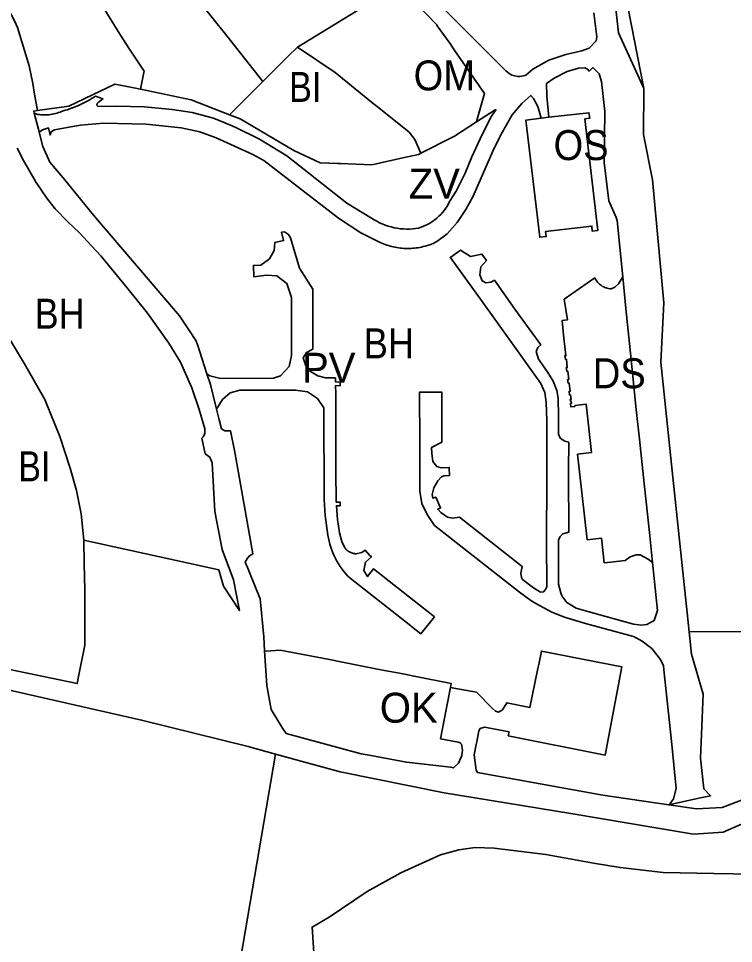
# Model space of a CAD drawing. Extents: x -650451 to -642268, y -1075216 to -1066610.
# Drawn here: x -645771.2 to -645413.5, y -1070883.4 to -1070420.9 of the extents above; entities that cross this region are included whole.
import ezdxf

# ---------------------------------------------------------------- set-up
doc = ezdxf.new("R2010")
doc.units = 0
doc.header["$LTSCALE"] = 6
doc.layers.add('1', color=7, linetype='Continuous', lineweight=35)
doc.layers.add('2', color=7, linetype='Continuous')
doc.layers.add('3', color=7, linetype='Continuous')

msp = doc.modelspace()

# ---------------------------------------------------------------- linework, layer by layer
at = {"layer": '1'}
for p, q in [((-645631.63, -1070435.3), (-645581.88, -1070404.79)), ((-645648.9, -1070452.38), (-645665.6, -1070469.04)), ((-645477.83, -1070467.43), (-645479.45, -1070452.44)), ((-645477.83, -1070467.43), (-645478.2, -1070492.9)), ((-645509.73, -1070470.79), (-645505.89, -1070470.28)), ((-645647.06, -1070549.3), (-645641.94, -1070549.53)), ((-645467.29, -1070565.95), (-645468.87, -1070550.15)), ((-645623.96, -1070586.18), (-645623.91, -1070556.28)), ((-645640.17, -1070599.5), (-645635.73, -1070594.86)), ((-645625.66, -1070597), (-645627.49, -1070594.56)), ((-645625.66, -1070597), (-645621.44, -1070599.65)), ((-645612.48, -1070608.38), (-645612.51, -1070604.47)), ((-645669.11, -1070611.38), (-645672.04, -1070616.26)), ((-645612.48, -1070608.38), (-645612.47, -1070611.33)), ((-645612.37, -1070644.92), (-645612.47, -1070611.33)), ((-645458.17, -1070653.38), (-645460.44, -1070631.3)), ((-645458.17, -1070653.38), (-645455.53, -1070677.99)), ((-645614.974, -1070685.241), (-645614.475, -1070686.701)), ((-645607.644, -1070685.968), (-645607.913, -1070685.639)), ((-645605.231, -1070687.804), (-645605.622, -1070687.603)), ((-645602.739, -1070688.492), (-645603.16, -1070688.44)), ((-645607.388, -1070698.566), (-645608.38, -1070697.401)), ((-645448.36, -1070746.61), (-645448.55, -1070744.43)), ((-645448.36, -1070746.61), (-645444.5, -1070782.23)), ((-645442.16, -1070805.9), (-645444.5, -1070782.23))]:
    msp.add_line(p, q, dxfattribs=at)
for points in [[(-645458.32, -1070455.91), (-645471, -1070391), (-645481.67, -1070345.39), (-645481.65, -1070342.07), (-645483.34, -1070321.17), (-645484.27, -1070309.7), (-645485.21, -1070298.03), (-645487.361, -1070271.37)], [(-645837.64, -1070295.83), (-645834.26, -1070303.42), (-645832.25, -1070305.65), (-645828.22, -1070310.11), (-645806.76, -1070328.54), (-645794.16, -1070338.86), (-645775.346, -1070326.977), (-645755.75, -1070371.21), (-645720.48, -1070428.75), (-645715.56, -1070436.27), (-645708.28, -1070447.28), (-645708.42, -1070447.94), (-645710.14, -1070456.31)], [(-645761.61, -1070466.87), (-645763.08, -1070458.8), (-645764.06, -1070453.46), (-645765.74, -1070444.55), (-645771.6, -1070425.37), (-645772.93, -1070422.45), (-645774.64, -1070419.2), (-645776.69, -1070415.31), (-645779.05, -1070410.84), (-645781.68, -1070407.25), (-645782.24, -1070406.48), (-645782.7, -1070405.88), (-645788.04, -1070398.98), (-645791.08, -1070394.9), (-645791.28, -1070394.68), (-645794.6, -1070391.11), (-645810.27, -1070374.27), (-645820.27, -1070363.94), (-645828.93, -1070354.9), (-645831.79, -1070351.94), (-645857.6, -1070325.28), (-645863.12, -1070319.59)], [(-645648.9, -1070452.38), (-645648.95, -1070452.32), (-645666.99, -1070429.58), (-645681.89, -1070410.81), (-645682.02, -1070410.65), (-645683.52, -1070411.71), (-645697.44, -1070391.91), (-645701.32, -1070386.14), (-645705.74, -1070379.56), (-645713.73, -1070365.9), (-645692.34, -1070349.34), (-645668.02, -1070330.52)], [(-645488.99, -1070362.96), (-645482.16, -1070375.96), (-645476.12, -1070393.13), (-645472.61, -1070413.13), (-645470.99, -1070428.07), (-645461.32, -1070449.31), (-645458.32, -1070455.91)], [(-645581.88, -1070404.79), (-645567.63, -1070418.2), (-645561.93, -1070424.15), (-645561.67, -1070424.51), (-645555.45, -1070433.22), (-645552.84, -1070437.12), (-645538.09, -1070458.33), (-645541.31, -1070470.02), (-645542.06, -1070472.61)], [(-645483.29, -1070417.99), (-645481.93, -1070430.04), (-645482.18, -1070432.13), (-645485.67, -1070435.7), (-645489.34, -1070437.05), (-645497.33, -1070438.82), (-645505.88, -1070441.74), (-645513.81, -1070446.24), (-645517.44, -1070449.23), (-645517.95, -1070449.45), (-645520.4, -1070449.87), (-645521.41, -1070449.84), (-645522.95, -1070449.61), (-645524.42, -1070449.16), (-645525.75, -1070448.41), (-645527.34, -1070447.1), (-645558.36, -1070416.1)], [(-645631.63, -1070435.3), (-645636.42, -1070439.93), (-645648.9, -1070452.38)], [(-645569.97, -1070488.3), (-645572.86, -1070481.41), (-645575.7, -1070477.77), (-645590.966, -1070465.607), (-645594.62, -1070462.7), (-645612.77, -1070447.82), (-645631.63, -1070435.3)], [(-645505.89, -1070470.28), (-645506.94, -1070459.72), (-645507.07, -1070453.47), (-645503.21, -1070450.74), (-645496.76, -1070447.39), (-645491.1, -1070445.67), (-645487.86, -1070445.62), (-645486.55, -1070446.19), (-645485.77, -1070447.23), (-645483.85, -1070445.46), (-645480.71, -1070448.54), (-645479.45, -1070452.44)], [(-645710.14, -1070456.31), (-645716.87, -1070454.93), (-645723.02, -1070453.66), (-645734.2, -1070459.05), (-645746.01, -1070464.75), (-645761.61, -1070466.87)], [(-645763.27, -1070468.21), (-645761.52, -1070468.88), (-645760.725, -1070468.979), (-645759.923, -1070469.051), (-645759.117, -1070469.095), (-645758.307, -1070469.111), (-645757.495, -1070469.099), (-645756.682, -1070469.058), (-645755.871, -1070468.989), (-645755.061, -1070468.891), (-645754.256, -1070468.765), (-645753.456, -1070468.61), (-645752.663, -1070468.428), (-645751.879, -1070468.218), (-645751.104, -1070467.982), (-645750.34, -1070467.72), (-645749.588, -1070467.432), (-645748.85, -1070467.12), (-645747.78, -1070466.818), (-645746.714, -1070466.494), (-645745.654, -1070466.148), (-645744.6, -1070465.779), (-645743.554, -1070465.389), (-645742.515, -1070464.976), (-645741.484, -1070464.542), (-645740.462, -1070464.086), (-645739.45, -1070463.609), (-645738.448, -1070463.111), (-645737.458, -1070462.593), (-645736.479, -1070462.055), (-645735.512, -1070461.497), (-645734.558, -1070460.92), (-645733.617, -1070460.324), (-645732.69, -1070459.71), (-645728.96, -1070461.09), (-645731.29, -1070462.95), (-645731.417, -1070463.016), (-645731.538, -1070463.102), (-645731.647, -1070463.206), (-645731.742, -1070463.326), (-645731.818, -1070463.459), (-645731.874, -1070463.599), (-645731.909, -1070463.743), (-645731.923, -1070463.886), (-645731.918, -1070464.03), (-645731.892, -1070464.175), (-645731.845, -1070464.319), (-645731.777, -1070464.456), (-645731.691, -1070464.582), (-645731.588, -1070464.692), (-645731.473, -1070464.786), (-645731.35, -1070464.86), (-645722.28, -1070464.74), (-645708.17, -1070465.09), (-645694.33, -1070466.36), (-645684.23, -1070467.84), (-645673.56, -1070470.8), (-645665.15, -1070474.28), (-645662.39, -1070475.35), (-645650.63, -1070481.24), (-645636.93, -1070489.64), (-645606.97, -1070513.16), (-645594.57, -1070520.71), (-645593.298, -1070521.526), (-645591.978, -1070522.287), (-645590.614, -1070522.989), (-645589.209, -1070523.628), (-645587.767, -1070524.201), (-645586.295, -1070524.705), (-645584.796, -1070525.137), (-645583.276, -1070525.497), (-645581.74, -1070525.781), (-645580.194, -1070525.989), (-645578.643, -1070526.122), (-645577.093, -1070526.179), (-645575.55, -1070526.16), (-645574.018, -1070526.068), (-645572.503, -1070525.904), (-645571.01, -1070525.67), (-645569.793, -1070525.275), (-645568.586, -1070524.813), (-645567.395, -1070524.286), (-645566.225, -1070523.693), (-645565.082, -1070523.035), (-645563.97, -1070522.316), (-645562.894, -1070521.536), (-645561.86, -1070520.699), (-645560.872, -1070519.809), (-645559.934, -1070518.869), (-645559.049, -1070517.883), (-645558.221, -1070516.856), (-645557.453, -1070515.794), (-645556.745, -1070514.7), (-645556.101, -1070513.58), (-645555.52, -1070512.44), (-645552.21, -1070507.22), (-645547.8, -1070498.2), (-645544.34, -1070490.01), (-645539.29, -1070478.88), (-645534.54, -1070469.76), (-645532.28, -1070466.32)], [(-645509.73, -1070470.79), (-645511.36, -1070464.95), (-645513.49, -1070460.97), (-645514.92, -1070459.32), (-645519.4, -1070463.48), (-645524.17, -1070469.11), (-645529.8, -1070479.03), (-645533.96, -1070487.3), (-645543.74, -1070509.74), (-645547.32, -1070516.32), (-645551.64, -1070522.86), (-645556.72, -1070528.54), (-645561.93, -1070532.44), (-645563.79, -1070533.39), (-645564.581, -1070533.705), (-645565.385, -1070534), (-645566.2, -1070534.277), (-645567.025, -1070534.533), (-645567.86, -1070534.768), (-645568.704, -1070534.983), (-645569.557, -1070535.175), (-645570.417, -1070535.346), (-645571.284, -1070535.495), (-645572.157, -1070535.621), (-645573.034, -1070535.723), (-645573.916, -1070535.803), (-645574.8, -1070535.859), (-645575.687, -1070535.891), (-645576.575, -1070535.9), (-645577.463, -1070535.885), (-645578.35, -1070535.847), (-645579.236, -1070535.784), (-645580.119, -1070535.698), (-645580.999, -1070535.589), (-645581.874, -1070535.457), (-645582.743, -1070535.301), (-645583.607, -1070535.123), (-645584.463, -1070534.922), (-645585.311, -1070534.7), (-645586.151, -1070534.456), (-645586.98, -1070534.191), (-645587.8, -1070533.906), (-645588.608, -1070533.6), (-645589.405, -1070533.275), (-645590.189, -1070532.932), (-645590.96, -1070532.57), (-645599.98, -1070528), (-645611.05, -1070520.81), (-645648.38, -1070491.95), (-645653.92, -1070488.85), (-645672.29, -1070480.56), (-645680.39, -1070477.65), (-645689.72, -1070475.58), (-645707.28, -1070473.72), (-645728.67, -1070473.29), (-645740.06, -1070474.19), (-645743.09, -1070474.76), (-645753.11, -1070476.57), (-645754.83, -1070477.59), (-645755.38, -1070479.08), (-645756.18, -1070475.61), (-645759.19, -1070476.56), (-645760.79, -1070477.75)], [(-645665.6, -1070469.04), (-645684.78, -1070461.52), (-645710.14, -1070456.31)], [(-645435.711, -1070727.497), (-645444.47, -1070643.85), (-645449.82, -1070592.72), (-645448.36, -1070563), (-645454.02, -1070501.52), (-645458.46, -1070478.86), (-645458.32, -1070455.91)], [(-645763.27, -1070468.21), (-645763.54, -1070467.17), (-645761.61, -1070466.87)], [(-645760.79, -1070477.75), (-645761.2, -1070476.16), (-645763.27, -1070468.21)], [(-645665.6, -1070469.04), (-645660.29, -1070471.12), (-645633.35, -1070486.91), (-645620.22, -1070493), (-645611.52, -1070493.37), (-645610.16, -1070493.43), (-645594.41, -1070494.08), (-645577.47, -1070490.3), (-645571.13, -1070488.89), (-645569.97, -1070488.3)], [(-645532.28, -1070466.32), (-645532.78, -1070466.64), (-645542.06, -1070472.61)], [(-645505.89, -1070470.28), (-645485.84, -1070468.01), (-645485.42, -1070470.79), (-645487.81, -1070471.13), (-645481.37, -1070526.93), (-645484.14, -1070527.28), (-645484.31, -1070524.66), (-645507.48, -1070527.34), (-645507.28, -1070529.96), (-645510.38, -1070530.29), (-645517.37, -1070471.66), (-645509.73, -1070470.79)], [(-645542.06, -1070472.61), (-645553.08, -1070479.7), (-645569.97, -1070488.3)], [(-645760.79, -1070477.75), (-645758.97, -1070484.82), (-645755.43, -1070492.66), (-645748.83, -1070500.53), (-645733.62, -1070519.2), (-645690.55, -1070569.6), (-645688.56, -1070572.64), (-645685.61, -1070577.02), (-645682.52, -1070581.87), (-645681.57, -1070583.92), (-645676.88, -1070598.59)], [(-645771.89, -1070485.66), (-645768.61, -1070491.93), (-645762.29, -1070502.85), (-645756.94, -1070510.81), (-645752.81, -1070516.11), (-645746.29, -1070522.79), (-645740.88, -1070527.97), (-645734.6, -1070534.63), (-645729.94, -1070539.58), (-645716.91, -1070555.35), (-645706.56, -1070568.19), (-645695.89, -1070583.17), (-645690.04, -1070592.67), (-645684.45, -1070605.57), (-645680.76, -1070616.33), (-645677.94, -1070626.03), (-645677.86, -1070628.21), (-645678.23, -1070629.21), (-645678.8, -1070630.03), (-645679.46, -1070630.75), (-645677.83, -1070638.56), (-645675.38, -1070640.29), (-645674.2, -1070643.07), (-645672.92, -1070667.42), (-645669.28, -1070686.41), (-645663.52, -1070701.56), (-645660.67, -1070716.93), (-645668.66, -1070704.8), (-645670.99, -1070696.59), (-645738.54, -1070681.67)], [(-645738.54, -1070681.67), (-645739.76, -1070668.59), (-645742.15, -1070656.97), (-645745.26, -1070645.72), (-645750.46, -1070629.86), (-645758.05, -1070611.4), (-645768.08, -1070593.53), (-645776.12, -1070580.27), (-645792.2, -1070553.77), (-645800.24, -1070540.51), (-645808.28, -1070527.27), (-645816.32, -1070514.02), (-645824.36, -1070500.76), (-645831.88, -1070488.37)], [(-645468.87, -1070550.15), (-645471.73, -1070521.93), (-645472.2, -1070520.36), (-645475.9, -1070512.13), (-645478.2, -1070492.9)], [(-645639.52, -1070527.73), (-645638.51, -1070531.91), (-645642.94, -1070532.95), (-645643.32, -1070536.98), (-645645.6, -1070541.03), (-645649.93, -1070544.17)], [(-645639.52, -1070527.73), (-645638.05, -1070527.53), (-645636.04, -1070528.83), (-645635.01, -1070530.52), (-645630.51, -1070545.8), (-645623.91, -1070556.28)], [(-645448.55, -1070744.43), (-645449.99, -1070741.54), (-645451.21, -1070739.85), (-645454.4, -1070735.98), (-645459.19, -1070732.3), (-645462.19, -1070730.5), (-645463.53, -1070729.98), (-645487.49, -1070723.42), (-645497.98, -1070720.16), (-645504.43, -1070717.68), (-645512.32, -1070713.33), (-645514.9, -1070711.87), (-645520.56, -1070707.79), (-645563, -1070674.39), (-645566.77, -1070668.94), (-645569.37, -1070663.42), (-645570.41, -1070657.25), (-645570.44, -1070633.21), (-645570.56, -1070607.66), (-645559.45, -1070607.71), (-645559.42, -1070632.82), (-645564.48, -1070635.35), (-645564.44, -1070638.26), (-645563.9, -1070642.47), (-645561.92, -1070644.94), (-645559.54, -1070645.51), (-645555.71, -1070645.39), (-645555.61, -1070649.48), (-645558.39, -1070649.6), (-645559.61, -1070650.14), (-645561.41, -1070652.05), (-645563.36, -1070655.51), (-645564.29, -1070658.96), (-645563.82, -1070660.8), (-645562.43, -1070660.23), (-645561.72, -1070661.77), (-645560.68, -1070664.11), (-645559.99, -1070665.62), (-645561.42, -1070666.27), (-645559.93, -1070667.85), (-645556.6, -1070670.16), (-645554.1, -1070670.79), (-645550.52, -1070670.21), (-645519.21, -1070694.89), (-645519.82, -1070698.19), (-645519.61, -1070700.46), (-645519.11, -1070701.39), (-645513.46, -1070705.56), (-645510.1, -1070707.67), (-645508.52, -1070707.65), (-645507.49, -1070706.46), (-645506.95, -1070705.03), (-645506.96, -1070682.29), (-645506.93, -1070651.11), (-645506.94, -1070622.09), (-645507.15, -1070612.93), (-645507.82, -1070607.9), (-645509.91, -1070603.33), (-645525.63, -1070581.2), (-645539.2, -1070562.35), (-645555.16, -1070540.29), (-645554.95, -1070540.26), (-645550.03, -1070536.72), (-645545.05, -1070539.94), (-645539.38, -1070538.66), (-645537.08, -1070541.92), (-645539.82, -1070545.06), (-645540.36, -1070549.11), (-645539.18, -1070551.99), (-645537.43, -1070553.01), (-645534.8, -1070552.67), (-645533.11, -1070551.79), (-645522.86, -1070566.18), (-645509.89, -1070584.1), (-645511.36, -1070585.42), (-645512.13, -1070587.38), (-645511.61, -1070589.63), (-645511.05, -1070591.31), (-645510.6, -1070591.9), (-645506.33, -1070597.84), (-645503.65, -1070602.19), (-645501.92, -1070606.98), (-645501.25, -1070610.78), (-645501.02, -1070619.82), (-645500.99, -1070625.75), (-645501.01, -1070628.79), (-645500.12, -1070630.71), (-645497.87, -1070632.29), (-645495.87, -1070632.81), (-645496, -1070646.36), (-645495.96, -1070648.03), (-645495.89, -1070677.71), (-645498.84, -1070678.61), (-645500.19, -1070679.84), (-645500.97, -1070681.8), (-645500.99, -1070703.81), (-645499.8, -1070708.06), (-645499.37, -1070709.57), (-645496.83, -1070712.83), (-645492.2, -1070715.68), (-645486.43, -1070717.48)], [(-645647.06, -1070549.3), (-645653.51, -1070550.01), (-645653.6, -1070544.35), (-645649.93, -1070544.17)], [(-645634.55, -1070560.44), (-645636.92, -1070553.36), (-645641.94, -1070549.53)], [(-645453.99, -1070692.88), (-645456.26, -1070691.25), (-645460.24, -1070689.15), (-645462.22, -1070689.01), (-645465.19, -1070690.01), (-645467.67, -1070691.87), (-645474.87, -1070692.74), (-645478.16, -1070693.14), (-645479.54, -1070680.67), (-645486.67, -1070681.54), (-645490.59, -1070647.61), (-645490.75, -1070646.01), (-645491.49, -1070638.79), (-645484.53, -1070637.98), (-645487.19, -1070613.79), (-645492.84, -1070614.42), (-645492.81, -1070614.88), (-645494.88, -1070615.07), (-645495.08, -1070613.33), (-645494.56, -1070613.26), (-645494.7, -1070612.17), (-645495.08, -1070612.22), (-645495.15, -1070611.38), (-645494.78, -1070611.36), (-645495.06, -1070609.1), (-645495.56, -1070609.16), (-645495.76, -1070607.36), (-645495.26, -1070607.33), (-645495.72, -1070603.18), (-645496.25, -1070603.23), (-645496.47, -1070601.42), (-645495.92, -1070601.39), (-645496.42, -1070597.2), (-645496.94, -1070597.25), (-645497.12, -1070595.47), (-645496.64, -1070595.38), (-645497.09, -1070591.24), (-645497.6, -1070591.26), (-645497.88, -1070589.46), (-645497.3, -1070589.44), (-645498.42, -1070580.7), (-645498.6, -1070579.19), (-645499.25, -1070571.93), (-645496.52, -1070571.56), (-645498.26, -1070561.27), (-645482.83, -1070550.63), (-645482.557, -1070551.178), (-645482.244, -1070551.716), (-645481.889, -1070552.239), (-645481.495, -1070552.742), (-645481.064, -1070553.221), (-645480.596, -1070553.673), (-645480.095, -1070554.093), (-645479.565, -1070554.477), (-645479.009, -1070554.823), (-645478.431, -1070555.129), (-645477.837, -1070555.391), (-645477.229, -1070555.611), (-645476.615, -1070555.785), (-645475.997, -1070555.916), (-645475.381, -1070556.004), (-645474.77, -1070556.05), (-645472.89, -1070555.29), (-645471.06, -1070553.59), (-645468.87, -1070550.15)], [(-645634.55, -1070560.44), (-645634.53, -1070589.43), (-645635.73, -1070594.86)], [(-645467.29, -1070565.95), (-645464.71, -1070591.33), (-645462.27, -1070614.86), (-645460.44, -1070631.3)], [(-645623.96, -1070586.18), (-645627.06, -1070587.88), (-645628.71, -1070590.62), (-645627.49, -1070594.56)], [(-645640.17, -1070599.5), (-645643.67, -1070600.77), (-645670.06, -1070600.85), (-645675.52, -1070599.54), (-645676.88, -1070598.59)], [(-645676.88, -1070598.59), (-645675.18, -1070603.92), (-645672.04, -1070616.26)], [(-645612.52, -1070600.61), (-645617.53, -1070600.63), (-645621.44, -1070599.65)], [(-645612.52, -1070600.61), (-645612.51, -1070602.61), (-645610.19, -1070602.7), (-645610.23, -1070604.51), (-645612.51, -1070604.47)], [(-645669.11, -1070611.38), (-645665.28, -1070608.14), (-645660.51, -1070606.77), (-645632.58, -1070606.68), (-645626.66, -1070607.61), (-645621.63, -1070610.87), (-645618.48, -1070615.64)], [(-645672.04, -1070616.26), (-645670.69, -1070621.55), (-645669.56, -1070625.99), (-645667.9, -1070627.04), (-645665.09, -1070627.11), (-645662.98, -1070637.66), (-645653.91, -1070688.62), (-645655.57, -1070689.58), (-645656.61, -1070690.71), (-645657.42, -1070692.11), (-645657.74, -1070692.82), (-645656.16, -1070696.6), (-645655.98, -1070697.02), (-645650.34, -1070711.07), (-645648.49, -1070730.06), (-645648.06, -1070737.06)], [(-645617.83, -1070669.4), (-645618.25, -1070661.44), (-645618.48, -1070615.64)], [(-645612.37, -1070644.92), (-645612.35, -1070646.95), (-645612.22, -1070662.75), (-645610.31, -1070662.66), (-645610.28, -1070664.52)], [(-645610.5, -1070678.09), (-645611.57, -1070671.42), (-645612.16, -1070664.56), (-645610.28, -1070664.52)], [(-645617.83, -1070669.4), (-645616.34, -1070679.3), (-645616.093, -1070680.793), (-645615.783, -1070682.283)], [(-645738.54, -1070681.67), (-645738.27, -1070693.6), (-645738.04, -1070706.52), (-645737.9, -1070733.79), (-645737.99, -1070734.24), (-645741.06, -1070749.97), (-645741.73, -1070753.43), (-645780.43, -1070745.4), (-645784.44, -1070740.92)], [(-645610.5, -1070678.09), (-645609.39, -1070682.34), (-645608.16, -1070685.3), (-645607.913, -1070685.639)], [(-645451.46, -1070716.89), (-645453.99, -1070692.88), (-645455.53, -1070677.99)], [(-645614.974, -1070685.241), (-645615.41, -1070683.767), (-645615.783, -1070682.283)], [(-645613.292, -1070689.56), (-645613.914, -1070688.142), (-645614.475, -1070686.701)], [(-645607.644, -1070685.968), (-645607.354, -1070686.283), (-645607.043, -1070686.584), (-645606.713, -1070686.868), (-645606.365, -1070687.134), (-645606.001, -1070687.379), (-645605.622, -1070687.603)], [(-645599.42, -1070687.99), (-645597.79, -1070686.69), (-645595.51, -1070689.22), (-645594.59, -1070690.02), (-645597.59, -1070692.68), (-645598.41, -1070696.88), (-645596.64, -1070699.96), (-645593.56, -1070696.04), (-645563.12, -1070720.01)], [(-645613.292, -1070689.56), (-645612.61, -1070690.953), (-645611.871, -1070692.316)], [(-645605.231, -1070687.804), (-645604.829, -1070687.981), (-645604.418, -1070688.134), (-645604.002, -1070688.261), (-645603.582, -1070688.363), (-645603.16, -1070688.44)], [(-645602.739, -1070688.492), (-645602.32, -1070688.52), (-645599.42, -1070687.99)], [(-645610.227, -1070694.938), (-645611.076, -1070693.645), (-645611.871, -1070692.316)], [(-645610.227, -1070694.938), (-645609.328, -1070696.191), (-645608.38, -1070697.401)], [(-645607.388, -1070698.566), (-645606.353, -1070699.683), (-645605.28, -1070700.75), (-645574.9, -1070724.61), (-645574.53, -1070724.94)], [(-645486.43, -1070717.48), (-645463.56, -1070723.81), (-645459.6, -1070724.28), (-645456.77, -1070723.99), (-645453.2, -1070721.89), (-645451.46, -1070716.89)], [(-645563.12, -1070720.01), (-645569.86, -1070728.57), (-645574.53, -1070724.94)], [(-645435.711, -1070727.497), (-645202.41, -1070726.571), (-645197.539, -1070753.128)], [(-645435.711, -1070727.497), (-645434.53, -1070738.77), (-645428.73, -1070758.67), (-645430, -1070790.68), (-645428.39, -1070806.09), (-645424.969, -1070809.563), (-645429.993, -1070810.647)], [(-645642.52, -1070788.7), (-645656.2, -1070784.96), (-645709.54, -1070771.74), (-645781.62, -1070755.42), (-645785.75, -1070754.48), (-645865, -1070735.66), (-645891.35, -1070731.13), (-645906.373, -1070728.716)], [(-645648.06, -1070737.06), (-645647.26, -1070737.17), (-645640.34, -1070736.72), (-645615.58, -1070741.49), (-645609.94, -1070742.59), (-645591.59, -1070746.19), (-645588.05, -1070746.85), (-645580.59, -1070748.22), (-645576.47, -1070749.04), (-645573.3, -1070749.75), (-645554.7, -1070753.41), (-645555.05, -1070755.49)], [(-645648.06, -1070737.06), (-645646.91, -1070754.37), (-645644.8, -1070766.37), (-645639.12, -1070775.74), (-645637.33, -1070778.34), (-645599.74, -1070788.56), (-645595.66, -1070789.32), (-645577.07, -1070792.77), (-645555.03, -1070795.23), (-645553.53, -1070795.66), (-645551.13, -1070793.3), (-645549.4, -1070789.42), (-645549.07, -1070786.78), (-645549.49, -1070783.81), (-645550.29, -1070783.02), (-645551.22, -1070782.7), (-645560.03, -1070781.11), (-645557.11, -1070765.58), (-645555.05, -1070755.49)], [(-645555.05, -1070755.49), (-645553.37, -1070755.82), (-645542.02, -1070757.79), (-645534.05, -1070765.87), (-645532.57, -1070767.28), (-645531.12, -1070767.68), (-645529.02, -1070766.53), (-645526.87, -1070763.04), (-645515.34, -1070765.49), (-645511.34, -1070745.83), (-645510.95, -1070743.9), (-645509.58, -1070737.17), (-645469.29, -1070745.15), (-645477.63, -1070789.21), (-645526.15, -1070779.53), (-645525.76, -1070777.58), (-645537.02, -1070775.46), (-645538.13, -1070775.3), (-645540.25, -1070775.93), (-645540.94, -1070777.05), (-645541.96, -1070782.5), (-645542.26, -1070783.94), (-645543.27, -1070789.16), (-645542.15, -1070796.73), (-645541.56, -1070797.841), (-645478.83, -1070809.27), (-645445.81, -1070814.06)], [(-645202.96, -1070752.89), (-645285.11, -1070750.69), (-645298.41, -1070751.48), (-645312.2, -1070753.77), (-645325.82, -1070757.94), (-645342.41, -1070765.76), (-645354.98, -1070774.28), (-645398.04, -1070805.44), (-645407.37, -1070810.95), (-645419.18, -1070815.44), (-645432.07, -1070816.05), (-645445.81, -1070814.06)], [(-645583.18, -1071010.7), (-645637.94, -1070997.4), (-645676.292, -1070985.89), (-645642.52, -1070788.7)], [(-645642.52, -1070788.7), (-645625, -1070793.5), (-645610.25, -1070797.55), (-645558.3, -1070808), (-645494.82, -1070818.45), (-645452.31, -1070825.52), (-645433.49, -1070828.76), (-645418.67, -1070827.72), (-645409.52, -1070823.76), (-645400.05, -1070819.84)], [(-645442.16, -1070805.9), (-645443.59, -1070811.12), (-645445.14, -1070813.46)], [(-645429.993, -1070810.647), (-645445.81, -1070814.06), (-645445.14, -1070813.46)], [(-645404.15, -1070848.781), (-645423.364, -1070848.402), (-645448.7, -1070847.895), (-645470.235, -1070845.487), (-645483.61, -1070843.208), (-645507.299, -1070838.899), (-645533.268, -1070835.731), (-645542.642, -1070835.35), (-645550.832, -1070836.602), (-645560.079, -1070839.137), (-645579.841, -1070848.008), (-645596.689, -1070857.387), (-645615.817, -1070870.187), (-645624.321, -1070875.224), (-645618.798, -1070958.861)]]:
    msp.add_lwpolyline(points, dxfattribs=at)

# ---------------------------------------------------------------- texts
at = {"layer": '2'}
for s, width, p in [('OM', 0.95, (-645573.5, -1070456.86)), ('OS', 0.95, (-645503.51, -1070491.7)), ('BH', 0.9, (-645763.11, -1070576.02)), ('BH', 0.9, (-645598.42, -1070590.85)), ('DS', 0.95, (-645483.87, -1070605.78)), ('BI', 0.85, (-645771.293, -1070652.319))]:
    msp.add_text(s, height=15, dxfattribs=dict(at, width=width)).set_placement(p)
for s, p in [('ZV', (-645575.98, -1070510.93)), ('PV', (-645629.336, -1070603.058)), ('OK', (-645590.43, -1070773.02))]:
    msp.add_text(s, height=15, dxfattribs=at).set_placement(p)
at = {"layer": '3', "width": 0.85}
msp.add_text('BI', height=15, dxfattribs=at).set_placement((-645635.78, -1070462.62))

doc.saveas('drawing.dxf')
